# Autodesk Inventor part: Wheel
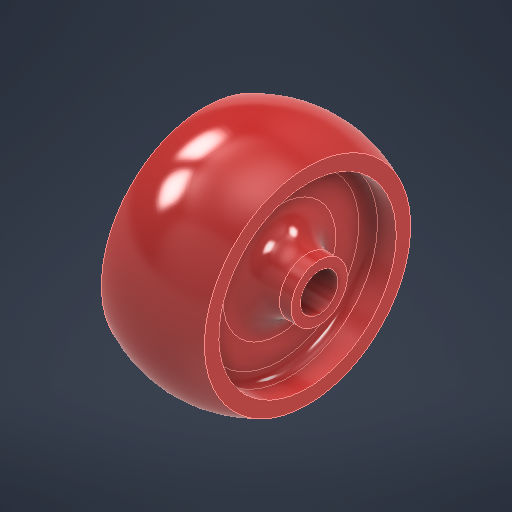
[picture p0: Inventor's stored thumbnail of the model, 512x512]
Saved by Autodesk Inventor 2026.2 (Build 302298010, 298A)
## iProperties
Created: 2021-06
Part Number: Wheel
Material: Generic
Document SubType Name: Modeling
Designer: ASUS
Density: 1 g/cm^3
Appearance: Orange-Red
Author: ASUS
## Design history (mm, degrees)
revolve "Revolution1" stored, may be unused: angle "d12" = 90 deg
fillet "Fillet1" dims "d13" = 6, "d14" = 2
body "Solid1"
sketch "Sketch1"
  geometry: L1 (-13.5, 0)-(13.5, 0); L2 (13.5, 0)-(13.5, 6); L3 (13.5, 6)-(5, 6); L4 (5, 6)-(5, 18.915); L5 (5, 18.915)-(11, 18.915); L6 (11, 18.915)-(11, 22); L7 (-11, 22)-(-11, 18.915); L8 (-11, 18.915)-(-5, 18.915); L9 (-5, 18.915)-(-5, 6); L10 (-5, 6)-(-13.5, 6); L11 (-13.5, 6)-(-13.5, 0); L12 (-13.5, 4)-(13.5, 4); A1 r 25 centre (0, -0.45) between (11, 22) and (-11, 22); 2 further points
  constraints: 24 end point, 9 perpendicular, 2 point on circle, 2 point on line, 2 vertical, 1 centre point, 1 coincident, 1 horizontal, 1 midpoint, 1 vertical alignment
  dimensions: "d0" = 27 distance of L1.start L1.end; "d1" = 8 diameter of L12 L1; "d2" = 12 diameter of L3 L1; "d3" = 37.83 diameter of L5 L1; "d4" = 25 radius of A1; "d5" = 2.5 horizontal distance of L12.end L5.end; "d6" = 6 distance of L4.end L5.end; "d7" = 6 distance of L7.end L8.end; "d8" = 12 diameter of L10 L1; "d9" = 2.5 distance between parallel lines of L11 L7; "d10" = 37.83 diameter of L8 L1; "d11" = 44 diameter of L7.start L1
